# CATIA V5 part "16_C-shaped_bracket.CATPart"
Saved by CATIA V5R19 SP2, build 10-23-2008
Part number: 16_C-shaped_bracket
Bounding box of the stored display mesh (mm): x -43.724 to 43.724, y -94.412 to 72.95, z -153.5 to 178
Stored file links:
  C:\Documents and Settings\anizard\Bureau\13\16_C-shaped_bracket.CATPart
  C:\Program Files (x86)\Dassault Systemes\B19\intel_a\reffiles\standard\MetricThickPitch.txt
  C:\Documents and Settings\anizard\Bureau\13\anizard.CATProduct
  D:\Documents\T\2011-2012\CFAO\ThinkMotion\7\SqueletteV.CATPart
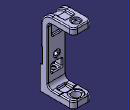
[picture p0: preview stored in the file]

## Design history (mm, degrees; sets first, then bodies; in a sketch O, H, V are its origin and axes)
External parameters (linked from other documents)
  External.da1 = 103.4604 mm
  External.da2 = 43.7239 mm
Set1
  Line1: linked copy from another document
  Point1: linked copy from another document
  Line2: linked copy from another document
  Line3: linked copy from another document
  Plane1: linked copy from another document
  Point2: linked copy from another document
  Plane2: linked copy from another document
  Point3 to Point5: linked copy from another document
  Line4: linked copy from another document
  Point6: linked copy from another document
  Plane3: linked copy from another document
  Line5: linked copy from another document
  Line6: linked copy from another document
  Plane4: linked copy from another document
  Plane5: linked copy from another document
  Point7: linked copy from another document
  Point8: linked copy from another document
  Plane6: linked copy from another document
  Point9 to Point11: linked copy from another document
  Plane7 to Plane9: linked copy from another document
  Point12: linked copy from another document
  Plane10: linked copy from another document
  Plane11: linked copy from another document
Body1 (main body)
  Sketch1 on yz-plane, origin (0, 0, 0), H (0, 1, 0), V (0, 0, 1)
    arc A1 centre (-29.5499, 127) radius 19.5 from (-49.0499, 127) to (-29.5499, 146.5) cw
    line L1 (-29.5499, 146.5) -> (72.9501, 146.5)
    line L2 (72.9501, 146.5) -> (72.9501, 178)
    line L3 (72.9501, 178) -> (-29.0499, 178)
    arc A2 centre (-29.0499, 127) radius 51 from (-29.0499, 178) to (-80.0499, 127) ccw
    line L4 (-87.0499, -153.5) -> (72.9501, -153.5)
    arc A3 centre (-30.0499, -101.5) radius 19 from (-30.0499, -120.5) to (-49.0499, -101.5) cw
    line L5 (-87.0499, 0) -> (-87.0499, -153.5)
    line L6 (-80.0499, 127) -> (-80.0499, 0)
    line L7 (-87.0499, 0) -> (-80.0499, 0)
    line L8 (-49.0499, -101.5) -> (-49.0499, 127)
    point P13 (72.9501, 178)
    point P14 (72.9501, 178)
    point P15 (72.9501, 146.5)
    point P16 (72.9501, 146.5)
    point P17 (72.9501, -153.5)
    point P18 (72.9501, -153.5)
    line L9 (72.9501, -153.5) -> (72.9501, -118.5)
    line L10 (72.9501, -118.5) -> (8.9501, -118.5)
    line L11 (8.9501, -118.5) -> (8.9501, -120.5)
    line L12 (8.9501, -120.5) -> (-30.0499, -120.5)
    point P21 (72.9501, -118.5)
    point P22 (72.9501, -118.5)
    reference projected point E1 (-49.0499, 0) from Point1
    reference projected line E2 (40.9501, -190) -> (40.9501, 190) from Line2
    reference projected point E3 (70.2001, -122.5) from Point3
    reference intersected line E4 through (0, 146.5) direction (-1, 0) from Plane1
    reference projected line E5 (58.5882, 0) -> (-208.4118, 0) from Line5
    reference projected line E6 (-66.0499, 9.7062) -> (-66.0499, -199.2938) from Line6
    reference intersected line E7 through (0, 178) direction (-1, 0) from Plane6
    reference projected line E8 (-66.0499, 9.7062) -> (-66.0499, -199.2938) from Line6
    reference intersected line E9 through (0, -153.5) direction (-1, 0) from Plane3
    reference intersected line E10 through (0, -118.5) direction (-1, 0) from Plane2
    radius A3 = 19
    radius A2 = 51
    distance L12 L10 = 2
    distance E3 L9 = 2.75
    distance E6 L5 = 21
    distance L6 E8 = 14
    tangency: L1 A1, A2 L3, L6 A2, L8 A1, A3 L8, L12 A3
    vertical: L2 V, L6 V, L8 V, L11 V
    horizontal: L3 H, L4 H, L7 H, L10 H, L1 H
    coincidence: L2 L9, P15 P16, P13 P14, L8 E1, P22 P21, P17 P18, L1 E4, L7 E5, L3 E7, L4 E9, L10 E10
    symmetry: L11 L9 E2
  Pad1: profile Sketch1, direction (1, 0, 0), length 43.7239 {= External.da2}, mirrored extent
  Sketch2 on face of Pad1 from Sketch1.L6, origin (0, -80.0499, 0), H (1, 0, 0), V (0, 0, 1)
    circle A1 centre (0, 0) radius 56.6616
    axis line L1 (97.0457, -56.6616) -> (-93.0451, -56.6616)
    reference projected point E1 (0, -51.6616) from Point12
    distance L1 E1 = 5
    horizontal: L1 H
    tangency: L1 A1
  Pocket1: profile Sketch2, direction (0, 1, 0), length 6
  Pocket2: profile Sketch2, direction (0, -1, 0), through (limit type 3)
  Sketch3 on face of Pad1 from Sketch1.L8, origin (0, -49.0499, 0), H (-1, 0, 0), V (0, 0, 1)
    line L1 (-19.8619, -31.2938) -> (19.8619, -31.2938)
    line L2 (24.3619, -35.7938) -> (24.3619, -62.2938)
    line L3 (19.8619, -66.7938) -> (-19.8619, -66.7938)
    line L4 (-24.3619, -62.2938) -> (-24.3619, -35.7938)
    arc A1 centre (19.8619, -35.7938) radius 4.5 from (19.8619, -31.2938) to (24.3619, -35.7938) cw
    arc A2 centre (-19.8619, -35.7938) radius 4.5 from (-19.8619, -31.2938) to (-24.3619, -35.7938) ccw
    arc A3 centre (-19.8619, -62.2938) radius 4.5 from (-19.8619, -66.7938) to (-24.3619, -62.2938) cw
    arc A4 centre (19.8619, -62.2938) radius 4.5 from (24.3619, -62.2938) to (19.8619, -66.7938) cw
    reference intersected line E1 through (0, -40.2938) direction (1, 0) from Plane4
    reference intersected line E2 through (0, -70.2938) direction (1, 0) from Plane5
    radius A1 = 4.5
    radius A2 = 4.5
    radius A3 = 4.5
    radius A4 = 4.5
    distance L1 E1 = 9
    distance L3 E2 = 3.5
    distance L2 L4 = 48.7239 {= External.da2 + 5 mm}
    horizontal: L1 H, L3 H
    vertical: L2 V, L4 V
    symmetry: L2 L4 V
    tangency: A1 L1, A1 L2, A2 L1, A2 L4, A3 L3, A3 L4, A4 L2, A4 L3
  Pocket3: profile Sketch3, direction (0, -1, 0), through (limit type 3)
  Sketch4 on end face of Pocket1, origin (0, -74.0499, 0), H (1, 0, 0), V (0, 0, 1)
    circle A1 centre (0, 0) radius 30
    radius A1 = 30
  Pad2: profile Sketch4, direction (0, -1, 0), length 11
  Sketch5 on end face of Pad2, origin (0, -85.0499, 0), H (1, 0, 0), V (0, 0, 1)
    circle A1 centre (0, 0) radius 13.5
    radius A1 = 13.5
  Pad3: profile Sketch5, direction (0, -1, 0), up to Plane9
  Fillet1: radius 4.5, on edge [end face of Pad2 | face of Pad3 from Sketch5.A1]
  Sketch6 on face of Pad1 from Sketch1.L4, origin (0, 0, -153.5), H (1, 0, 0), V (0, -1, 0)
    circle A1 centre (0, 66.0499) radius 14
    reference projected point E1 (0, 66.0499) from Point7
    reference projected point E2 (0, 52.0499) from Point8
    concentricity: A1 E1
    coincidence: A1 E2
  Pocket4: profile Sketch6, direction (0, 0, 1), up to Plane5
  Sketch7 on end face of Pocket4, origin (0, 0, -70.2938), H (1, 0, 0), V (0, -1, 0)
    circle A1 centre (0, 66.0499) radius 11
    reference projected circle E1 centre (0, 66.0499) radius 14 from edge [face of Pad1 from Sketch1.L4 | face of Pocket4 from Sketch6.A1]
    radius A1 = 11
    concentricity: A1 E1
  Pocket5: profile Sketch7, direction (0, 0, -1), through (limit type 6)
  Sketch8 on face of Pad1 from Sketch1.L3, origin (0, 109, 178), H (1, 0, 0), V (0, 1, 0)
    point P1 (0, -68.0499)
    reference projected point E1 (0, -68.0499) from Line2
    coincidence: E1 P1
  Hole1: placed by Sketch8, at (0, 40.9501, 178) direction (0, 0, -1), diameter 23.5 {= distance(Point9 ,Point10 )*2}, through (limit type 6), counterbore diameter 41 {= distance(Point9 ,Point11 )*2}, counterbore depth 8
  Sketch9 on Plane2, origin (0, 109, -118.5), H (1, 0, 0), V (0, 1, 0)
    point P1 (0, -68.0499)
    reference projected point E1 (0, -68.0499) from Point5
    coincidence: P1 E1
  Hole2: placed by Sketch9, at (0, 40.9501, -118.5) direction (0, 0, -1), diameter 38 {= distance(Line4 ,Point6  ) *2}, up to Plane3, counterbore diameter 58.5 {= distance(Line4  ,Point3  )*2}, counterbore depth 4
  Sketch10 on face of Pad1 from Sketch1.L8, origin (0, -49.0499, 0), H (1, 0, 0), V (0, 0, -1)
    point P1 (0, 0)
    reference projected point E1 (0, 0) from Line1
    coincidence: E1 P1
  Hole3: placed by Sketch10, at (0, -49.0499, 0) direction (0, -1, 0), diameter 20, through (limit type 6), counterbore diameter 33, counterbore depth 3.5 {= distance(Point1 ,Plane10 )}
  Sketch11 on yz-plane, origin (0, 0, 0), H (0, 1, 0), V (0, 0, 1)
    line L1 (-80.0499, 82) -> (-72.0499, 82)
    line L2 (-72.0499, 82) -> (-72.0499, 127)
    arc A1 centre (-29.0499, 127) radius 43 from (-72.0499, 127) to (-29.0499, 170) cw
    line L3 (-29.0499, 170) -> (10.9501, 170)
    line L4 (10.9501, 170) -> (10.9501, 178)
    line L5 (10.9501, 178) -> (-80.0499, 178)
    line L6 (-80.0499, 178) -> (-80.0499, 82)
    reference projected arc E1 centre (-29.0499, 127) radius 51 from (-29.0499, 178) to (-80.0499, 127) ccw from edge [face of Pad1 from Sketch1.A2 | end face of Pad1]
    reference projected line E2 (136.5, 178) -> (19.5, 178) from edge [face of Pad1 from Sketch1.L3 | end face of Pad1]
    reference projected line E3 (-80.0499, 127) -> (-80.0499, 0) from edge [face of Pad1 from Sketch1.L6 | end face of Pad1]
    reference projected line E4 (72.9501, 151) -> (72.9501, 173.5) from edge [face of Pad1 from Sketch1.L2 | end face of Pad1]
    point P9 (0, 82)
    line L7 (0, 82) -> (-56.5499, 82)
    line L8 (-56.5499, 82) -> (-56.5499, 127)
    arc A2 centre (-29.0499, 127) radius 27.5 from (-56.5499, 127) to (-29.0499, 154.5) cw
    line L9 (-29.0499, 154.5) -> (10.9501, 154.5)
    point P14 (10.9501, 154.5)
    line L10 (10.9501, 154.5) -> (10.9501, 146.5)
    point P15 (10.9501, 146.5)
    line L11 (10.9501, 146.5) -> (0, 82)
    reference projected line E5 (19.5, 146.5) -> (136.5, 146.5) from edge [face of Pad1 from Sketch1.L1 | end face of Pad1]
    reference projected line E6 (19.5, 146.5) -> (136.5, 146.5) from edge [face of Pad1 from Sketch1.L1 | end face of Pad1]
    line L12 (-29.0499, -120.5) -> (8.9501, -120.5)
    line L13 (8.9501, -120.5) -> (8.9501, -128.5)
    line L14 (8.9501, -128.5) -> (-29.0499, -128.5)
    line L15 (-29.0499, -128.5) -> (-29.0499, -120.5)
    line L16 (-29.0499, -153.5) -> (8.9501, -153.5)
    line L17 (8.9501, -153.5) -> (8.9501, -145.5)
    line L18 (8.9501, -145.5) -> (-29.0499, -145.5)
    line L19 (-29.0499, -145.5) -> (-29.0499, -153.5)
    point P22 (8.9501, -145.5)
    reference projected line E7 (77, -120.5) -> (19, -120.5) from edge [face of Pad1 from Sketch1.L12 | end face of Pad1]
    reference projected line E8 (-38, -153.5) -> (136.5, -153.5) from edge [face of Pad1 from Sketch1.L4 | end face of Pad1]
    reference projected line E9 (8.9501, -118.5) -> (8.9501, -120.5) from edge [face of Pad1 from Sketch1.L11 | end face of Pad1]
    reference projected line E10 (58.5882, 0) -> (-208.4118, 0) from Line5
    reference projected point E11 (-30.0499, -120.5) from vertex [face of Pad1 from Sketch1.A3 | end face of Pad1 | face of Pad1 from Sketch1.L12]
    distance L2 L6 = 8
    distance L4 E4 = 62
    distance E6 L9 = 8
    distance L14 L12 = 8
    distance L16 L18 = 8
    distance L7 E10 = 82
    distance E11 L15 = 1
    horizontal: L1 H, L5 H, L3 H, L7 H, L9 H, L12 H, L14 H, L16 H, L18 H
    vertical: L2 V, L4 V, L6 V, L8 V, L10 V, L13 V, L15 V, L17 V, L19 V
    tangency: A1 L2, L3 A1, A2 L8, L9 A2
    concentricity: A1 E1, A2 A1
    coincidence: L5 E2, L6 E3, P9 L1, P9 V, P14 L4, P15 E5, P22 L13, L19 L15, L12 E7, L16 E8, L13 E9
  Pocket6: profile Sketch11, direction (-1, 0, 0), length 21, mirrored extent
  Fillet2: radius 4.5, on face of Pocket6 from Sketch11.L4; end face of Pocket6 (x3); face of Pocket6 from Sketch11.L1; start face of Pocket6 (x3); face of Pocket6 from Sketch11.L10; face of Pocket6 from Sketch11.L7; face of Pocket6 from Sketch11.L15; face of Pocket6 from Sketch11.L17; face of Pocket6 from Sketch11.L19; edge [face of Pad1 from Sketch1.L12 | end face of Pocket6]; edge [face of Pocket6 from Sketch11.L14 | end face of Pocket6]; edge [start face of Pocket6 | face of Pad1 from Sketch1.L12]; edge [start face of Pocket6 | face of Pocket6 from Sketch11.L14]
  Fillet3: radius 20, on edge [face of Pad1 from Sketch1.L9 | end face of Pad1]; edge [start face of Pad1 | face of Pad1 from Sketch1.L9]; edge [face of Pad1 from Sketch1.L2 | end face of Pad1]; edge [start face of Pad1 | face of Pad1 from Sketch1.L2]
  Fillet4: radius 4.5, on edge [face of Pad1 from Sketch1.L3 | end face of Pad1]; edge [face of Pad1 from Sketch1.L4 | end face of Pad1]; edge [face of Pad1 from Sketch1.L12 | end face of Pad1]; edge [face of Pad1 from Sketch1.L4 | face of Pad1 from Sketch1.L5]; edge [face of Pad1 from Sketch1.L5 | end face of Pad1]; edge [start face of Pad1 | face of Pad1 from Sketch1.L5]; edge [face of Pad1 from Sketch1.L5 | face of Pocket3 from Sketch3.L3]; edge [face of Pad1 from Sketch1.L8 | face of Pocket3 from Sketch3.L3]
  Sketch12 on face of Pad1 from Sketch1.L8, origin (0, -49.0499, 0), H (-1, 0, 0), V (0, 0, 1)
    arc A1 centre (0, -31.2938) radius 8 from (-8, -31.2938) to (8, -31.2938) cw
    point P1 (0, -31.2938)
    point P2 (-8, -31.2938)
    point P3 (8, -31.2938)
    reference projected line E1 (19.5, -31.2938) -> (-19.5, -31.2938) from edge [face of Pad1 from Sketch1.L8 | face of Pocket3 from Sketch3.L1]
    reference projected line E2 (19.5, -31.2938) -> (-19.5, -31.2938) from edge [face of Pad1 from Sketch1.L8 | face of Pocket3 from Sketch3.L1]
    reference projected line E3 (19.5, -31.2938) -> (-19.5, -31.2938) from edge [face of Pad1 from Sketch1.L8 | face of Pocket3 from Sketch3.L1]
    line L1 (8, -31.2938) -> (-8, -31.2938)
    radius A1 = 8
    coincidence: P3 E1, P1 E2, P2 E3
    horizontal: L1 H
    symmetry: P3 P2 V
  Pocket7: profile Sketch12, direction (0, -1, 0), length 29.5
  Sketch13 on yz-plane, origin (0, 0, 0), H (0, 1, 0), V (0, 0, 1)
    line L1 (-52.5999, -150.1) -> (-50.5999, -150.1)
    line L2 (-50.5999, -150.1) -> (-50.5999, -151.4)
    line L3 (-50.5999, -151.4) -> (-52.5999, -151.4)
    line L4 (-52.5999, -151.4) -> (-52.5999, -150.1)
    reference projected line E1 (-66.0499, 0) -> (-66.0499, -190) from Line3
    reference intersected line E2 through (0, -151.4) direction (1, 0) from Plane7
    reference intersected line E3 through (0, -150.1) direction (1, 0) from Plane8
    distance L2 E1 = 15.45
    distance L4 L2 = 2
    horizontal: L1 H, L3 H
    vertical: L2 V, L4 V
    coincidence: L3 E2, L1 E3
  Groove1: profile Sketch13, axis Line3, angle 360
  Fillet5: radius 4.5, on edge [face of Pocket6 | face of Pocket6 from Sketch11.L14]
  Sketch14 on face of Hole1, origin (0, 124, 170), H (1, 0, 0), V (0, 1, 0)
    point P1 (0, -68.0499)
    reference projected point E1 (0, -68.0499) from Point2
    coincidence: P1 E1
  Hole4: placed by Sketch14, at (0, 55.9501, 170) direction (0, 0, -1), diameter 3.242, through (limit type 6), threaded "M4", thread diameter 4, thread depth 20, pitch 0.7
  CircPattern1: of Hole4, instances 6, angular step 72, axis from Line2
  Sketch15 on Plane11, origin (0, 81.5882, -122.5), H (1, 0, 0), V (0, 1, 0)
    point P1 (0, -17.6381)
    reference projected point E1 (0, -17.6381) from Point4
    coincidence: P1 E1
  Hole5: placed by Sketch15, at (0, 63.9501, -122.5) direction (0, 0, -1), diameter 3.242, up to Plane3, threaded "M4", thread diameter 4, thread depth 20, pitch 0.7
  CircPattern2: of Hole5, instances 6, angular step 72, axis from Line2
  Fillet6: radius 4.5, on edge [face of Pocket6 | face of Pad1 from Sketch1.L10]; edge [face of Pad1 from Sketch1.L10 | end face of Pad1]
